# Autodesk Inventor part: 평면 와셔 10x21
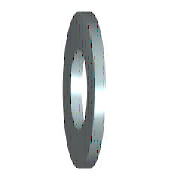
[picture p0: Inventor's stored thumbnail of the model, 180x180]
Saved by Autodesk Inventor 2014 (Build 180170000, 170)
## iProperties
IsCustomPart: 1
Created: 2012-02
Part Number: 평면 와셔 10x21
Material: 강철, 연강
Description: 평면 와셔
Document SubType Name: Modeling
Standard: KS B 1326
Designer: mduedu
Standards Organization: KS
Language: ko-KR
Size Designation: 10x21
Categories: <MemberInstance><Categories><Category DisplayName="조임쇠" InternalName="e4da775c-781d-43d5-af7c-5136215cf5a6" Mnemonic="FSTN"><Category DisplayName="와셔" InternalN
Density: 1 g/cm^3
Appearance: Yellow
Author: mduedu
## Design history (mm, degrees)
sketch "스케치"
  geometry: C1 r 10.5 at (0, 0); C2 r 5.25 at (0, 0); 1 further point
  constraints: 2 centre point, 2 coincident
  dimensions: "d0" = 10.5 diameter of C2 (= SD1); "d1" = 21 diameter of C1 (= SD2)
extrude "본체" new body sketch "스케치" distance "d2" = 2 (= SD); taper "d3" = 0 deg
workaxis "Work Axis1"
workplane "Work Plane1"
body "Solid1"
other parameters: "SD1" = 10.5 [user parameter; used in 1 equation term], "SD2" = 21 [user parameter; used in 1 equation term], "SD" = 2 [user parameter; used in 1 equation term], "d4" = 0, "d5" = 0, "d6" = 0, "d7" = 0
